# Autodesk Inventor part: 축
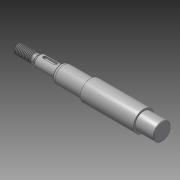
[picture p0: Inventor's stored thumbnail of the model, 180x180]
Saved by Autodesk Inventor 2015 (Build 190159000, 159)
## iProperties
Created: 2015-11
Part Number: 축
Material: 강철, 연강
Document SubType Name: Modeling
Designer: mduedu
Density: 1 g/cm^3
Appearance: 강철
Author: mduedu
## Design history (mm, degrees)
sketch "스케치1"
  geometry: L1 (-86, 0)-(86, 0); L2 (-86, 0)-(-86, 4); L3 (-86, 4)-(-70.732, 4); L4 (-70.732, 4)-(-69, 3); L5 (-69, 3)-(-67, 3); L6 (-67, 3)-(-67, 5); L7 (-67, 5)-(-49, 5); L8 (-49, 5)-(-49, 6.55); L9 (-47.355, 7.5)-(-23, 7.5); L10 (-23, 7.5)-(-23, 9); L11 (0, 0)-(0, 9); L12 (86, 4)-(70.732, 4); L13 (70.732, 4)-(69, 3); L14 (69, 3)-(67, 3); L15 (67, 3)-(67, 5); L16 (67, 5)-(49, 5); L17 (23, 7.5)-(23, 9); L18 (86, 0)-(86, 4); L19 (-23, 9)-(23, 9); L20 (-49, 6.55)-(-47.355, 7.5); L21 (47.355, 7.5)-(23, 7.5); L22 (49, 6.55)-(47.355, 7.5); L23 (49, 5)-(49, 6.55); 1 further point
  constraints: 46 end point, 10 symmetric about line, 6 perpendicular, 5 parallel, 2 midpoint, 1 coincident, 1 horizontal
  dimensions: "d0" = 172 distance of L1.start L1.end (derived); "d1" = 8 diameter of L3 L1; "d2" = 30 deg angle of L4 L5; "d3" = 6 diameter of L5 L1; "d4" = 10 diameter of L7 L1; "d5" = 15 diameter of L9 L1; "d6" = 18 diameter of L19 L1; "d8" = 18 distance of L6.end L7.end; "d9" = 46 distance of L10.end L17.end; "d10" = 2 distance of L4.end L5.end; "d11" = 17 distance from line of L4.end L2; "d16" = 13.1 diameter of L8.end L1; "d17" = 30 deg angle of L20 L9; "d18" = 26 distance between parallel lines of L10 L8
revolve "회전1" sketch "스케치1" stored, may be unused: angle "d12" = 90 deg
chamfer "모따기1" distance "d13" = 0.5; stored, may be unused: second distance "d14" = 2, angle "d15" = 45 deg
fillet "모깎기1" dims "d19" = 4, "d20" = 0.5
node "작업 평면1"
sketch "스케치2" dims "d23" = 12
  geometry: L1 (-4.5, 1.5)-(4.5, 1.5); L2 (4.5, 1.5)-(4.5, -1.5); L3 (4.5, -1.5)-(-4.5, -1.5); L4 (-4.5, -1.5)-(-4.5, 1.5); L5 (-9, -4.5)-(-9, 4.5) reference; 3 further points
  constraints: 8 end point, 2 midpoint, 2 parallel, 2 vertical alignment, 1 horizontal, 1 perpendicular, 4 other
  dimensions: "d21" = 3 distance between parallel lines of L3 L1; "d24" = 3 dimension on L5
extrude "돌출1" cut sketch "스케치2" distance "d25" = 1.8; taper "d26" = 0 deg
feature "스레드1" dims "d27" = 10, "d28" = 0
feature "스레드2" dims "d29" = 10, "d30" = 0
chamfer "모따기2" distance "d31" = 0.5; stored, may be unused: second distance "d32" = 2, angle "d33" = 45 deg
node "작업 평면2"
sketch "스케치3"
  geometry: C1 r 7.5 at (0, 0) reference; 1 further point
extrude "돌출2" cut sketch "스케치3" stored distance "d36" = 10; taper "d37" = 0 deg
chamfer "모따기3" distance "d38" = 0.5; stored, may be unused: second distance "d39" = 2, angle "d40" = 45 deg
fillet "모깎기3" dims "d41" = 0.6
node "솔리드1"
mirror "대칭1"
node "절단 모서리 투영1"
other parameters: "d35" = 16
